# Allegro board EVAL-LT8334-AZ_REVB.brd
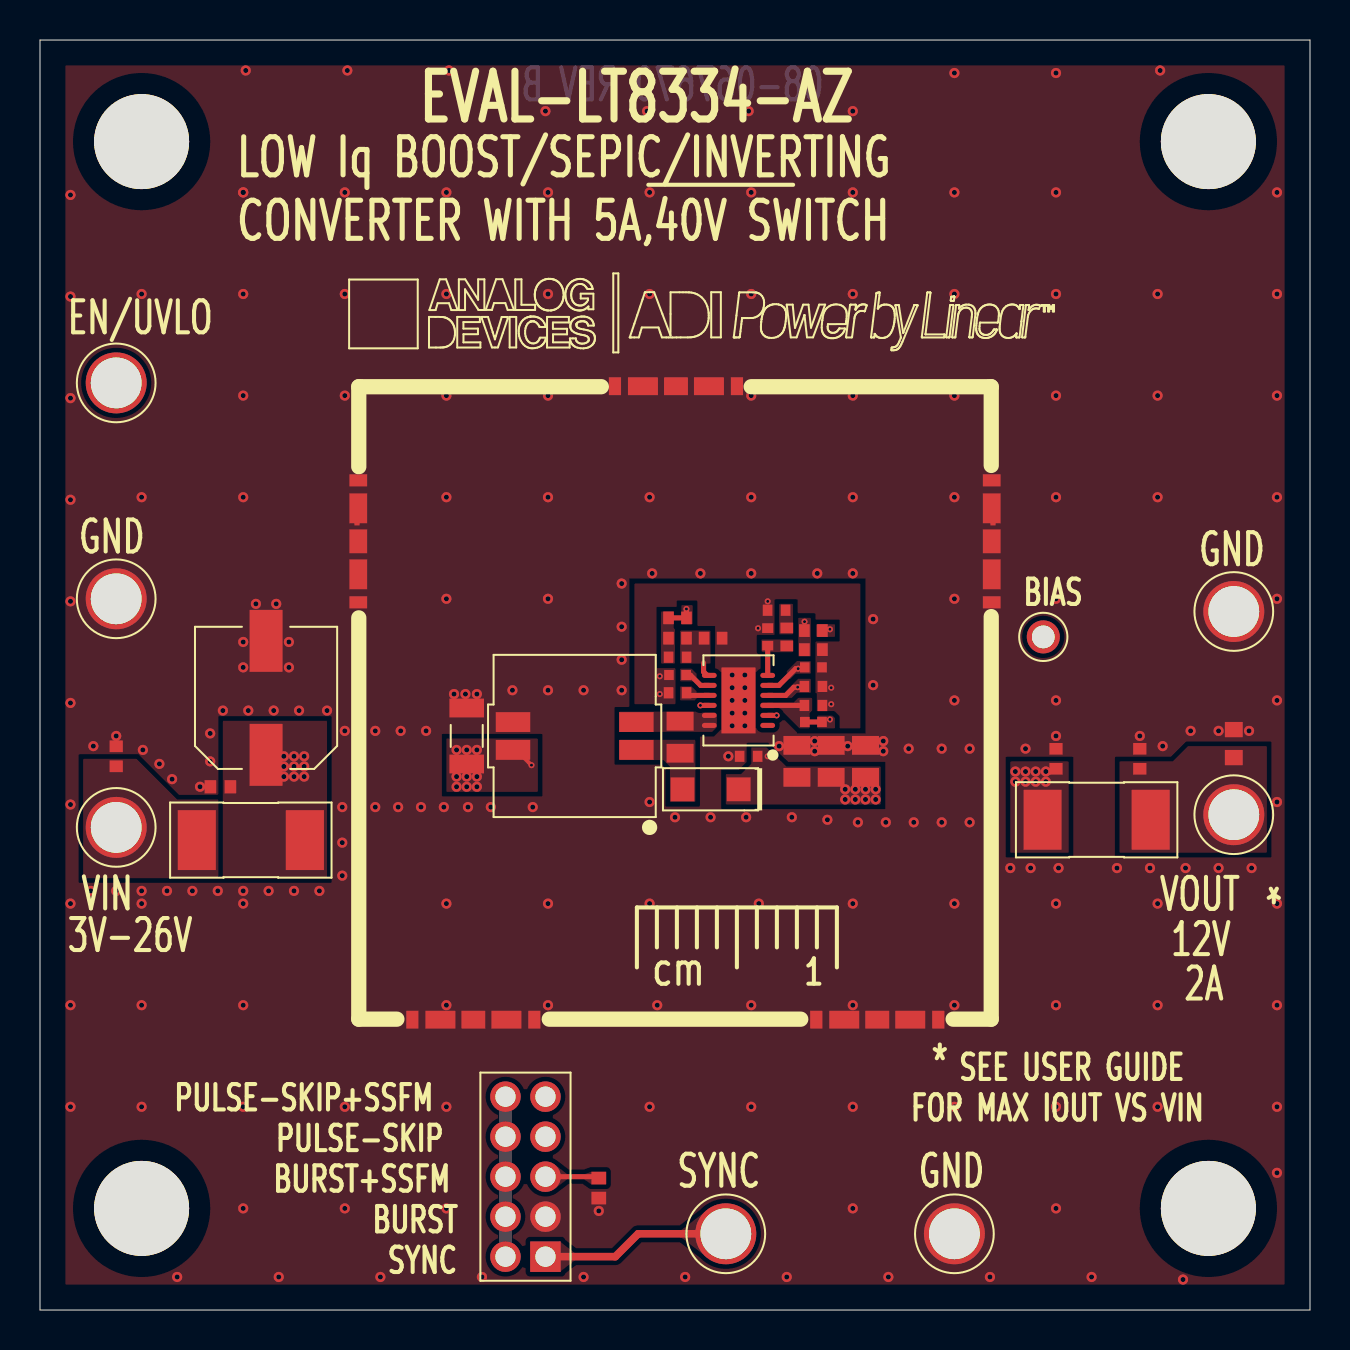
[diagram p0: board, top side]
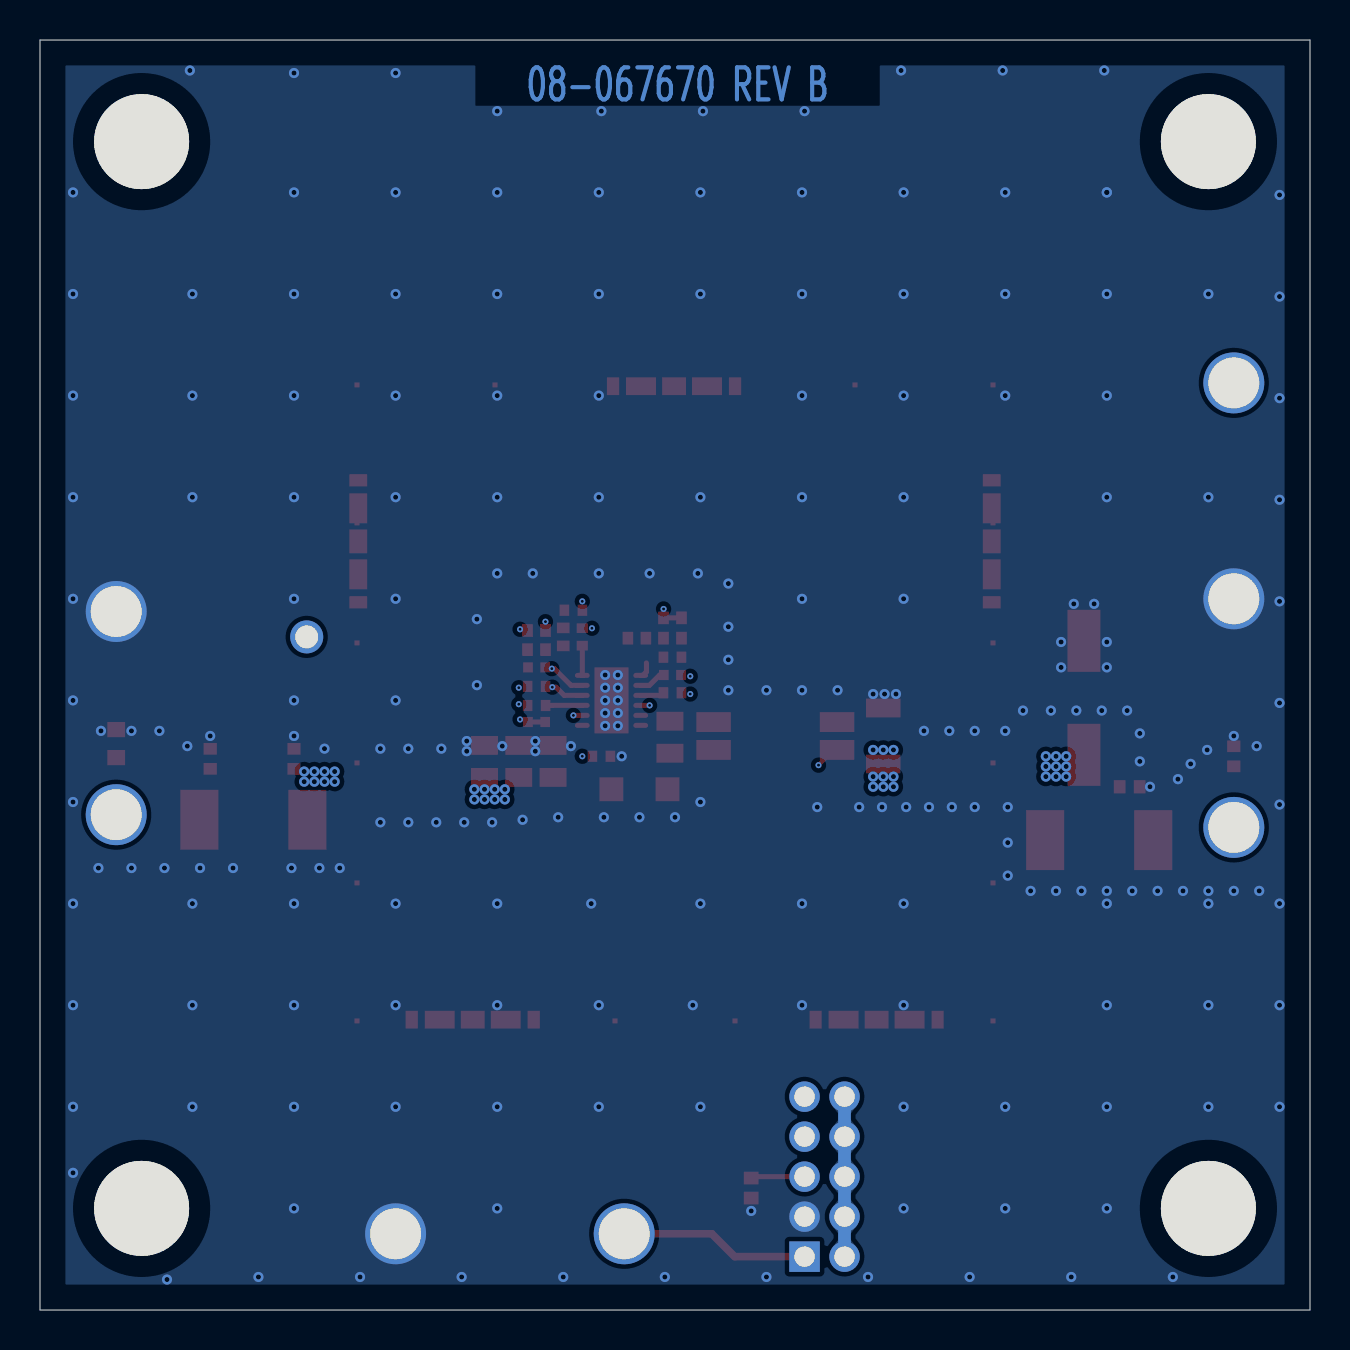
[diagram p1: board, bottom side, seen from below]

Outline 63.5 x 63.5 mm; copper layers: TOP, LAYER_2, LAYER_3, BOTTOM. Coordinates in mm from the lower left corner of the outline.
Outline path: 0,63.5 0,0 63.5,0 63.5,63.5 0,63.5

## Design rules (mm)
constraint set DEFAULT: min track width 0.203

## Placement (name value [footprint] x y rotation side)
C1  0.1UF  [C0402]  3.81 27.69 90 top
C2  0.1UF  [C0402]  9.02 26.16 180 top
C3  0.1uF  [C0402]  31.88 30.86 0 top
C4  10uF  [C1206H71]  21.34 28.7 90 top
C5  0.1UF  [C0402]  38.67 30.23 0 top
C6  4.7uF  [C0805H55]  32 28.64 270 top
C7  1000pF  [C0402]  36.83 34.99 180 top
C8  1UF  [C0402]  38.67 31.18 0 top
C9  4.7pF  [C0402]  31.88 32.64 0 top
C10  2.2UF  [C0402]  35.43 27.69 180 top
C11  22uF  [C0805H60]  37.85 27.43 90 top
C12  2.2UF  [C0402]  50.8 27.56 90 top
C13  2.2UF  [C0402]  54.99 27.56 90 top
C14  1uF  [C0603]  59.69 28.32 270 top
C15  TBD0402  [C0402#2]  36.39 33.66 90 top
C16  68UF  [CPLSMSQ260H315]  11.3 30.61 90 top
C17  22uF  [C0805H60]  41.27 27.43 90 top
C18  22uF  [C0805H60]  39.56 27.43 90 top
CL1  36900000  [CNWURTH36900000]  15.91 38.43 90 top
CL2  36900000  [CNWURTH36900000]  31.8 46.19 0 top
CL3  36900000  [CNWURTH36900000]  41.86 14.52 0 top
CL4  36900000  [CNWURTH36900000]  47.59 38.43 90 top
CL5  36900000  [CNWURTH36900000]  21.67 14.52 180 top
D1  PMEG4030ER,115  [SOD123F]  33.53 26.04 180 top
E1  2501-2-00-80-00-00-07-0  [CNMILLMAX2501]  3.81 24.13 180 top
E2  2501-2-00-80-00-00-07-0  [CNMILLMAX2501]  3.81 35.56 180 top
E3  2501-2-00-80-00-00-07-0  [CNMILLMAX2501]  3.81 46.35 180 top
E4  2501-2-00-80-00-00-07-0  [CNMILLMAX2501]  34.29 3.81 180 top
E5  2501-2-00-80-00-00-07-0  [CNMILLMAX2501]  45.72 3.81 180 top
E6  2501-2-00-80-00-00-07-0  [CNMILLMAX2501]  59.69 24.77 180 top
E7  2501-2-00-80-00-00-07-0  [CNMILLMAX2501]  59.69 34.92 180 top
FB1  880OHM AT 100MEGHZ  [L1812H67]  10.54 23.5 0 top
FB2  785OHM AT 100MEGHZ  [L1812H67]  52.83 24.51 0 top
JP1  87758-1016  [CNTHMHDR2X5L390W157H234]  25.27 2.67 90 top
L1  1.986UH/7.944UH  [LSMSQ299H175_4P]  26.73 28.7 90 top
NOREF  -  []  -187.47 299.61 0 top
NOREF#2  -  []  -178.82 342.9 0 top
NOREF#3  -  []  20.32 -7.62 0 top
NOREF#4  -  []  53.98 -5.08 270 top
NOREF#5  -  []  -192.41 353.69 0 top
NOREF#6  -  []  -188.47 53.59 0 top
NOREF#7  -  []  63.5 0 90 top
NOREF#8  -  [unnamed#2]  58.42 58.42 0 top
NOREF#9  -  []  348.62 318.77 0 top
NOREF#10  -  []  76.2 344.81 0 top
NOREF#11  -  []  -222.25 -146.05 0 top
NOREF#12  -  []  -188.7 330.83 0 top
NOREF#13  -  []  -222.25 -146.05 0 top
NOREF#14  -  []  29.84 20.13 0 top
NOREF#15  -  []  63.5 63.5 180 top
NOREF#16  -  [unnamed#2]  58.42 5.08 0 top
NOREF#17  -  []  -66.04 -72.39 0 top
NOREF#18  -  []  0 0 0 top
NOREF#19  -  [unnamed#2]  5.08 58.42 0 top
NOREF#20  -  []  -222.25 -146.05 0 top
NOREF#21  -  []  0 63.5 0 top
NOREF#22  -  [unnamed#2]  5.08 5.08 0 top
NOREF#23  -  []  63.5 0 90 top
NOREF#24  -  []  0 63.5 270 top
R1  1.15MEG  [R0402#2]  38.67 33.02 0 top
R2  20K  [R0402]  31.88 31.75 180 top
R3  1MEG  [R0402#2]  38.67 33.97 0 top
R4  22K  [R0402#2]  37.34 33.66 90 top
R5  0  [R0402]  38.67 32.13 0 top
R6  1MEG  [R0402#2]  31.88 33.59 180 top
R7  154K  [R0402#2]  33.66 33.59 180 top
R8  100K  [R0402#2]  27.94 6.1 90 top
R9  TBD0402  [R0402#2]  31.88 34.61 0 top
R10  TBD0402  [R0402]  38.67 29.4 0 top
SH1  36906326S  [M36906326S]  31.75 30.35 0 top
TP1  TESTPAD  [TPC65D45]  50.16 33.66 180 top
U1  LT8334RDE#PBF  [DFN12_4X3_PAD3_3X1_7]  34.92 30.48 90 top

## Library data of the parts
C1 C2 C5 = CAP: User Part Number: UPN; Tolerance: 10; alternate symbols: (C0402L); part number: CAP_SM-0.1UF,50V,10,E048331,C0402; tolerance: 10
C3 = CAP: User Part Number: UPN; Tolerance: 10; alternate symbols: (C0402L); part number: CAP_SM-0.1UF,25V,10,E025708,C0402; tolerance: 10
C4 = CAP: Tolerance: 20; User Part Number: UPN; alternate symbols: (C1206H71L); part number: CAP_SM-10UF,50V,20,E034660,C1206H71; tolerance: 20
C6 = CAP: User Part Number: UPN; Tolerance: 10; alternate symbols: (C0805L); part number: CAP_SM-4.7UF,50V,10,E042974,C0805H55; tolerance: 10
C7 = CAP: User Part Number: UPN; Tolerance: 10; alternate symbols: (C0402L); part number: CAP_SM-1000PF,10V,10,E038307,C0402; tolerance: 10
C8 = CAP: User Part Number: UPN; Tolerance: 10; alternate symbols: (C0402L); part number: CAP_SM-1UF,25V,10,E054542,C0402; tolerance: 10
C9 = CAP: User Part Number: UPN; Tolerance: 0.25pF; alternate symbols: (C0402L); part number: CAP_SM-4.7PF,50V,0.25PF,E041689,C0402; tolerance: 0.25pF
C10 C12 C13 = CAP: User Part Number: UPN; Tolerance: 10; alternate symbols: (C0402L); part number: CAP_SM-2.2UF,25V,10,E044855,C0402; tolerance: 10
C11 C17 C18 = CAP: User Part Number: UPN; Tolerance: 20; alternate symbols: (C0805L); part number: CAP_SM-22UF,25V,20,E028881,C0805H60; tolerance: 20
C14 = CAP: User Part Number: UPN; Tolerance: 10; alternate symbols: (C0603L); part number: CAP_SM-1UF,25V,10,E034292,C0603; tolerance: 10
C15 = CAP: User Part Number: UPN; alternate symbols: (C0402L_ALT,C0402L); part number: CAP_SM-TBD0402,TBD0402,TBD0402,E000381,C0402
C16 = CAPP: Tolerance: 20; User Part Number: UPN; alternate symbols: (); part number: CAPP_SM-68UF,35V,20,E054539,CPLSMSQ260H315; tolerance: 20
CL1-CL5 = CN5P: User Part Number: UPN; Tolerance: N/A; alternate symbols: (); part number: CN5P_SM-36900000,E054569,CNWURTH36900000; tolerance: N/A
D1 = DIOSCHOTTKY: Tolerance: N/A; User Part Number: UPN; alternate symbols: (); part number: DIOSCHOTTKY_SM-PMEG4030ER,115,40V,N/A,E017661,SOD123F; tolerance: N/A
E1-E7 = CNTP1P: User Part Number: UPN; Tolerance: N/A; alternate symbols: (); part number: CNTP1P_TH-2501-2-00-80-00-00-07-0,E031108,CNMILLMAX2501; tolerance: N/A
FB1 = FERRITE: User Part Number: UPN; Tolerance: 25; alternate symbols: (L1812H67L); part number: FERRITE_SM-880OHM AT 100MEGHZ,25,E050126,L1812H67; tolerance: 25
FB2 = FERRITE: User Part Number: UPN; Tolerance: 25; alternate symbols: (); part number: FERRITE_SM-785OHM AT 100MEGHZ,25,E038761,L1812H67; tolerance: 25
JP1 = CN10P: User Part Number: UPN; Tolerance: N/A; alternate symbols: (); part number: CN10P_TH-87758-1016,E032028,CNTHMHDR2X5L390W157H234; tolerance: N/A
L1 = IND_4P_V4: Tolerance: 20; User Part Number: UPN; alternate symbols: (); part number: IND_4P_V4_SM-1.986UH/7.944UH,20,E054540,LSMSQ299H175_4P; tolerance: 20
R1 = RES: User Part Number: UPN; Tolerance: 1; alternate symbols: (R0402L); part number: RES_SM-1.15MEG,E050592,1/16W,1,R0402; tolerance: 1
R2 = RES: Tolerance: 1; User Part Number: UPN; alternate symbols: (R0402L,R0402L_ALT); part number: RES_SM-20K,E003791,1/10W,1,R0402; tolerance: 1
R3 R6 = RES: User Part Number: UPN; Tolerance: 1; alternate symbols: (R0402L); part number: RES_SM-1MEG,E003749,1/10W,1,R0402; tolerance: 1
R4 = RES: User Part Number: UPN; Tolerance: 1; alternate symbols: (R0402L); part number: RES_SM-22K,E046831,1/10W,1,R0402; tolerance: 1
R5 = RES: Tolerance: JUMPER; User Part Number: UPN; alternate symbols: (R0402L,R0402L_ALT); part number: RES_SM-0,E003438,1/10W,JUMPER,R0402; tolerance: JUMPER
R7 = RES: User Part Number: UPN; Tolerance: 1; alternate symbols: (R0402L); part number: RES_SM-154K,E025222,1/10W,1,R0402; tolerance: 1
R8 = RES: User Part Number: UPN; Tolerance: 1; alternate symbols: (R0402L,R0402L_ALT); part number: RES_SM-100K,E003796,1/10W,1,R0402; tolerance: 1
R9 R10 = RES: User Part Number: UPN; alternate symbols: (R0402L,R0402L_ALT); part number: RES_SM-TBD0402,E004049,TBD0402,TBD0402,R0402
SH1 = MOD_SHLD_20P: User Part Number: UPN; Tolerance: N/A; alternate symbols: (); part number: MOD_SHLD_20P_SM-36906326S,E054570,M36906326S; tolerance: N/A
TP1 = NCTESTPAD: Tolerance: N/A; User Part Number: UPN; alternate symbols: (); part number: NCTESTPAD_TH-TESTPAD,E013404,TPC65D45; tolerance: N/A
U1 = ADLT8334: User Part Number: UPN; Tolerance: N/A; alternate symbols: (); part number: ADLT8334_SM-LT8334RDE#PBF,E050027,DFN12_4X3_PAD3_3X1_7; tolerance: N/A

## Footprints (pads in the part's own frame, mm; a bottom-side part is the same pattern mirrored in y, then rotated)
C0402
  rect 0.584x0.66 smd: 1(-0.5,0) 2(0.5,0)
C0402#2
  rect 0.483x0.559 smd: 1(-0.438,0) 2(0.438,0)
C0603
  rect 0.762x0.889 smd: 1(-0.7,0) 2(0.7,0)
C0805H55
  rect 0.94x1.346 smd: 1(-0.8,0) 2(0.8,0)
C0805H60
  rect 0.94x1.346 smd: 1(-0.8,0) 2(0.8,0)
C1206H71
  rect 0.94x1.727 smd: 1(-1.4,0) 2(1.4,0)
CNMILLMAX2501
  round 3.048 hole 2.54: 1(0,0)
CNTHMHDR2X5L390W157H234
  rect 1.524x1.524 hole 1.016: 1(0,0)
  round 1.524 hole 1.016: 2(0,2) 3(2,0) 4(2,2) 5(4,0) 6(4,2) 7(6,0) 8(6,2) 9(8,0) 10(8,2)
CNWURTH36900000
  rect 0.61x0.889 smd: 1(-3.05,0) 5(3.05,0)
  rect 1.499x0.889 smd: 2(-1.65,0) 4(1.65,0)
  rect 1.194x0.889 smd: 3(0,0)
CPLSMSQ260H315
  rect 3.099x1.651 smd: N(2.85,0) P(-2.85,0)
DFN12_4X3_PAD3_3X1_7
  oval 0.254x0.737 smd: 1(-1.25,-1.46) 2(-0.75,-1.46) 3(-0.25,-1.46) 4(0.25,-1.46) 5(0.75,-1.46) 6(1.25,-1.46) 7(1.25,1.46) 8(0.75,1.46) 9(0.25,1.46) 10(-0.25,1.46) 11(-0.75,1.46) 12(-1.25,1.46)
  rect 3.302x1.702 smd: PAD(0,0)
L1812H67
  rect 1.905x2.997 smd: 1(-2.703,0) 2(2.703,0)
LSMSQ299H175_4P
  rect 0.991x1.727 smd: 1(-0.695,-3.086) 2(0.695,-3.086) 3(0.695,3.086) 4(-0.695,3.086)
M36906326S
  rect 0.254x0.254 smd: 1(-15.9,-15.9) 2(-9,-15.9) 3(-3,-15.9) 4(3,-15.9) 5(9,-15.9) 6(15.9,-15.9) 7(15.9,-9) 8(15.9,-3) 9(15.9,3) 10(15.9,9) 11(15.9,15.9) 12(9,15.9) 13(3,15.9) 14(-3,15.9) 15(-9,15.9) 16(-15.9,15.9) 17(-15.9,9) 18(-15.9,3) 19(-15.9,-3) 20(-15.9,-9)
R0402
  rect 0.483x0.508 smd: 1(-0.43,0) 2(0.43,0)
R0402#2
  rect 0.533x0.635 smd: 1(-0.45,0) 2(0.45,0)
SOD123F
  rect 1.194x1.194 smd: A(1.403,0) C(-1.403,0)
TPC65D45
  round 1.651 hole 1.143: 1(0,0)
unnamed#2
  round 4.75 hole 4.75 unplated: (0,0)

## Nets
GND_POWER: C1.2(N2) C2.2(N2) C3.1 C4.2(N2) C5.2(N2) C7.2(N2) C8.2(N2) C10.2(N2) C11.2(N2) C12.2(N2) C13.2(N2) C14.1 C15.2(N2) C16.N(N2) C17.2(N2) C18.2(N2) CL1.1 CL1.2 CL1.3 CL1.4 CL1.5(N5) CL2.1 CL2.2 CL2.3 CL2.4 CL2.5(N5) CL3.1 CL3.2 CL3.3 CL3.4 CL3.5(N5) CL4.1 CL4.2 CL4.3 CL4.4 CL4.5(N5) CL5.1 CL5.2 CL5.3 CL5.4 CL5.5(N5) E2.1(N1) E5.1(N1) E7.1(N1) JP1.3 L1.3 R1.2(N2) R2.2(N2) R5.2(N2) R7.1 R8.1 SH1.1 SH1.2 SH1.3 SH1.4 SH1.5 SH1.6 SH1.7 SH1.8 SH1.9(SHIELD_9) SH1.10 SH1.11 SH1.12 SH1.13 SH1.14 SH1.15 SH1.16 SH1.17 SH1.18 SH1.19 SH1.20 U1.PAD
INTVCC: C8.1 JP1.9(N9) U1.4
UNNAMED_2_ADLT8334_I42_BIAS: R5.1 TP1.1(N1) U1.5
UNNAMED_2_ADLT8334_I42_EN: E3.1(N1) R1.1 R3.1 U1.2
UNNAMED_2_ADLT8334_I42_FBX: C9.2(N2) R6.1 R7.2(N2) U1.7
UNNAMED_2_ADLT8334_I42_RT: R2.1 U1.8
UNNAMED_2_ADLT8334_I42_SS: C3.2(N2) U1.9
UNNAMED_2_ADLT8334_I42_SW1: C6.1 L1.2 U1.11 U1.12
UNNAMED_2_ADLT8334_I42_SYNC: JP1.2 JP1.4 JP1.6 JP1.8 JP1.10 U1.10
UNNAMED_2_ADLT8334_I42_VC: C15.1 R4.1 U1.6
UNNAMED_2_CAP_I5_N1: C1.1 E1.1(N1) FB1.1
UNNAMED_2_CAP_I9_N1: C2.1 C4.1 C5.1 C16.P FB1.2(N2) L1.4(N4) R3.2(N2) R10.1 R10.2(N2) U1.3(VIN)
UNNAMED_2_CAP_I28_N2: C13.1 C14.2(N2) E6.1(N1) FB2.2(N2)
UNNAMED_2_CAP_I53_N2: C6.2(N2) D1.A(P) L1.1
UNNAMED_2_CAP_I84_N1: C7.1 R4.2(N2)
UNNAMED_2_CN10P_I40_N1: E4.1(N1) JP1.1
UNNAMED_2_CN10P_I40_N5: JP1.5 R8.2(N2)
VOUT: C9.1 C10.1 C11.1 C12.1 C17.1 C18.1 D1.C FB2.1 R6.2(N2) R9.1 R9.2(N2)

Pads without a net: JP1 7; U1 1

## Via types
v1: diameter 0.508, hole 0.254, TOP to BOTTOM, 264 vias
v2: diameter 0.305, hole 0.152, TOP to BOTTOM, 16 vias

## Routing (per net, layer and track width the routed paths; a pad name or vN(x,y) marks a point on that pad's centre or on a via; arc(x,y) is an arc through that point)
GND_POWER:
  vias: v1(1.52,55.75) v1(1.52,50.67) v1(1.52,45.59) v1(1.52,40.51) v1(1.52,35.43) v1(1.52,30.35) v1(1.52,25.27) v1(1.52,20.32) v1(1.52,15.24) v1(1.52,10.16) v1(2.54,20.95) v1(2.67,28.19) v1(3.81,28.7) v1(3.81,20.95) v1(5.08,50.8) v1(5.08,40.64) v1(5.14,28) v1(5.08,20.95) v1(5.08,20.32) v1(5.08,15.24) v1(5.08,10.16) v1(5.97,27.3) v1(6.35,20.95) v1(6.6,26.54) v1(6.86,1.65) v1(7.62,20.95) v1(8,26.16) v1(8.51,28.83) v1(8.51,27.43) v1(8.89,20.95) v1(9.14,29.97) v1(10.16,55.88) v1(10.16,55.88) v1(10.16,50.8) v1(10.16,45.72) v1(10.16,40.64) v1(10.16,33.4) v1(10.16,32.13) v1(10.16,20.95) v1(10.16,20.32) v1(10.16,15.24) v1(10.16,10.16) v1(10.16,5.08) v1(10.29,61.98) v1(10.41,29.97) v1(10.79,35.31) v1(11.43,20.95) v1(11.68,29.97) v1(11.81,35.31) v1(11.94,1.65) v1(12.45,33.4) v1(12.45,32.13) v1(12.7,20.95) v1(12.95,29.97) v1(13.97,20.95) v1(14.35,29.97) v1(15.11,25.15) v1(15.11,23.37) v1(15.11,21.72) v1(15.24,55.88) v1(15.24,50.8) v1(15.24,45.72) v1(15.24,28.96) v1(15.24,10.16) v1(15.24,5.08) v1(15.37,61.98) v1(16.76,28.96) v1(16.76,25.15) v1(17.02,1.65) v1(17.91,25.15) v1(18.03,28.96) v1(19.05,25.15) v1(19.3,28.96) v1(20.19,25.15) v1(20.32,55.88) v1(20.32,50.8) v1(20.32,45.72) v1(20.32,40.64) v1(20.32,35.56) v1(20.32,20.32) v1(20.32,15.24) v1(20.32,10.16) v1(20.32,5.08) v1(20.45,61.98) v1(20.7,30.8) v1(21.27,30.8) v1(21.4,25.15) v1(21.84,30.8) v1(22.1,1.65) v1(22.54,25.15) v1(23.62,30.99) v1(24.64,25.15) v1(25.27,59.94) v1(25.4,55.88) v1(25.4,50.8) v1(25.4,45.72) v1(25.4,40.64) v1(25.4,35.56) v1(25.4,30.99) v1(25.4,20.32) v1(25.4,15.24) v1(27.18,30.99) v1(27.18,1.65) v1(27.94,4.95) v1(29.08,36.32) v1(29.08,34.16) v1(29.08,32.51) v1(29.08,30.99) v1(30.35,59.94) v1(30.48,55.88) v1(30.48,50.8) v1(30.48,40.64) v1(30.48,25.4) v1(30.48,20.32) v1(30.48,10.16) v1(30.61,36.83) v1(30.86,15.24) v1(31.75,24.64) v1(32.26,1.65) v1(33.02,36.83) v1(33.53,24.64) v1(34.42,27.69) v1(34.61,31.75) v1(34.61,31.11) v1(34.61,30.48) v1(34.61,29.84) v1(34.61,29.21) v1(35.24,31.75) v1(35.24,31.11) v1(35.24,30.48) v1(35.24,29.84) v1(35.24,29.21) v1(35.31,24.64) v1(35.43,59.94) v1(35.56,55.88) v1(35.56,50.8) v1(35.56,45.72) v1(35.56,40.64) v1(35.56,36.83) v1(35.56,15.24) v1(35.56,10.16) v1(35.94,20.32) v1(36.96,28.19) v1(37.34,1.65) v1(37.59,24.64) v1(38.73,28.45) v1(38.73,27.94) v1(38.86,36.83) v1(39.37,24.51) v1(40.39,28.19) v1(40.64,59.94) v1(40.64,55.88) v1(40.64,50.8) v1(40.64,45.72) v1(40.64,40.64) v1(40.64,36.83) v1(40.64,20.32) v1(40.64,15.24) v1(40.64,10.16) v1(40.64,5.08) v1(40.89,24.38) v1(41.66,34.54) v1(41.66,31.24) v1(42.16,28.45) v1(42.16,27.94) v1(42.29,24.38) v1(42.42,1.65) v1(43.43,28.07) v1(43.69,24.38) v1(45.09,28.07) v1(45.09,24.38) v1(45.72,61.85) v1(45.72,55.88) v1(45.72,50.8) v1(45.72,45.72) v1(45.72,40.64) v1(45.72,35.56) v1(45.72,30.48) v1(45.72,20.32) v1(45.72,15.24) v1(45.72,10.16) v1(46.48,28.07) v1(46.48,24.38) v1(47.5,1.65) v1(48.51,22.1) v1(49.28,28.07) v1(49.53,22.1) v1(50.8,61.85) v1(50.8,55.88) v1(50.8,50.8) v1(50.8,45.72) v1(50.8,40.64) v1(50.8,35.56) v1(50.8,30.48) v1(50.8,28.7) v1(50.8,20.32) v1(50.8,15.24) v1(50.8,10.16) v1(50.8,5.08) v1(50.93,22.1) v1(52.58,1.65) v1(53.85,22.1) v1(54.99,28.7) v1(55.5,22.1) v1(55.88,50.8) v1(55.88,45.72) v1(55.88,40.64) v1(55.88,20.32) v1(55.88,15.24) v1(55.88,10.16) v1(56.01,61.98) v1(56.13,28.19) v1(57.15,1.52) v1(57.28,22.1) v1(57.53,28.96) v1(58.93,28.96) v1(58.93,22.1) v1(60.45,28.96) v1(60.58,22.1) v1(61.85,55.88) v1(61.85,50.8) v1(61.85,45.72) v1(61.85,40.64) v1(61.85,35.56) v1(61.85,30.48) v1(61.85,25.4) v1(61.85,20.32) v1(61.85,15.24) v1(61.85,10.16) v1(61.85,6.86) v2(30.99,31.69) v2(30.99,30.8) v2(35.9,34.09) v2(36.39,35.43) v2(39.56,31.11) v2(39.56,30.29)
INTVCC: length 31.9
  TOP w0.254: U1.4 37.29,30.73 37.7,31.14 v2(37.88,31.14) 38.08,31.14
  LAYER_3 w0.254: v2(37.88,31.14) 38.32,31.14 38.93,31.75 40.07,31.75 40.51,31.31 40.51,29.27 39.56,28.32 39.56,27.62 27.94,16 27.94,13.33 JP1.9
UNNAMED_2_ADLT8334_I42_BIAS: length 14.8
  TOP w0.254: v2(37.91,32.07) 37.78,32.07 36.95,31.23 U1.5
  LAYER_3 w0.254: v2(37.91,32.07) 38.48,32.64 39.31,32.64 40.32,33.66 TP1.1
UNNAMED_2_ADLT8334_I42_EN: length 47.2
  TOP w0.254: U1.2 v2(36.83,29.73)
  LAYER_3 w0.254: v2(36.83,29.73) 36.63,29.73 35.97,30.39 35.97,32.74 37.64,34.42 v2(38.23,34.42) 38.16,36.07 27.88,46.35 E3.1
UNNAMED_2_ADLT8334_I42_FBX: length 0.8
  TOP w0.254: U1.7 33.36,31.73 33.18,31.91 33.18,32.35
UNNAMED_2_ADLT8334_I42_RT: length 1.4
  TOP w0.254: U1.8 33.03,31.23 32.51,31.75 R2.1
UNNAMED_2_ADLT8334_I42_SS: length 1.2
  TOP w0.254: C3.2 32.46,30.73 U1.9
UNNAMED_2_ADLT8334_I42_SYNC: length 36.1
  TOP w0.254: U1.10 v2(33.02,30.23)
  LAYER_3 w0.381: JP1.10 23.27,27.46 25.4,29.59 32.38,29.59 v2(33.02,30.23)
  BOTTOM w0.635: JP1.10 JP1.8 JP1.6 JP1.4 JP1.2
UNNAMED_2_ADLT8334_I42_VC: length 1.5
  TOP w0.254: U1.6 36.39,31.73 C15.1
UNNAMED_2_CAP_I9_N1: length 27.7
  TOP w0.203: v2(24.57,27.24) 23.81,28.01 L1.4
  TOP w0.254: U1.3 37.9,30.23 C5.1 ; R10.1 R10.2
  LAYER_3 w0.241: 36.93,30.84 37.78,29.98
  LAYER_3 w0.254: 37.88,29.53 37.88,29.89 37.78,29.98 ; 37.88,29.53 37.88,27.84 36.77,26.73 25.08,26.73 v2(24.57,27.24) ; 37.88,29.53 v2(39.5,29.53) ; 36.93,30.84 36.93,32.38 38.07,33.53 38.67,33.53 39.18,34.04 v2(39.5,34.04)
  vias: v1(12.19,27.69) v1(12.19,27.18) v1(12.19,26.67) v1(12.7,27.69) v1(12.7,27.18) v1(12.7,26.67) v1(13.21,27.69) v1(13.21,27.18) v1(13.21,26.67) v1(20.83,28) v1(20.83,26.67) v1(20.83,26.16) v1(21.34,28) v1(21.34,26.67) v1(21.34,26.16) v1(21.84,28) v1(21.84,26.67) v1(21.84,26.16)
UNNAMED_2_CN10P_I40_N1: length 9.5
  TOP w0.381: JP1.1 28.77,2.67 29.91,3.81 E4.1
UNNAMED_2_CN10P_I40_N5: length 2.7
  TOP w0.254: JP1.5 27.87,6.67 R8.2
VOUT: length 11.2
  TOP w0.254: v2(32.32,35.05) R9.2 R9.1
  LAYER_3 w0.254: v2(32.32,35.05) 32.32,32.77 33.96,31.13 33.96,28.78 34.29,28.45 35.62,28.45 v2(36.39,27.69)
  vias: v1(40.26,26.04) v1(40.26,25.53) v1(40.77,26.04) v1(40.77,25.53) v1(41.27,26.04) v1(41.27,25.53) v1(41.78,26.04) v1(41.78,25.53) v1(48.77,26.92) v1(48.77,26.42) v1(49.28,26.92) v1(49.28,26.42) v1(49.78,26.92) v1(49.78,26.42) v1(50.29,26.92) v1(50.29,26.42)

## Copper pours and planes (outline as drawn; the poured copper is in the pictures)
GND_POWER on TOP: 1.27,62.23 62.23,62.23 62.23,1.27 1.27,1.27 ; 3 cut-outs
GND_POWER on BOTTOM: 1.27,62.23 62.23,62.23 62.23,1.27 1.27,1.27 ; 6 cut-outs
GND_POWER on LAYER_2: 1.27,62.23 62.23,62.23 62.23,1.27 1.27,1.27 ; 1 cut-out
GND_POWER on LAYER_3: 1.27,62.23 62.23,62.23 62.23,1.27 1.27,1.27 ; 6 cut-outs
INTVCC on TOP: 38.54,31.56 38.54,30.86 37.85,30.86 37.59,30.61 37.27,30.61 37.27,30.92 37.91,31.56
UNNAMED_2_ADLT8334_I42_BIAS on TOP: 38.54,32.45 38.54,31.81 37.78,31.81 37.53,31.56 37.34,31.56 37.34,31.94 37.85,32.45
UNNAMED_2_ADLT8334_I42_EN on TOP: 37.91,34.61 37.91,32.64 38.54,32.64 38.54,34.61
UNNAMED_2_ADLT8334_I42_FBX on TOP: 32,33.97 32,32.32 33.53,32.32 33.53,33.97
UNNAMED_2_ADLT8334_I42_SW1 on TOP: 33.85,29.91 33.85,29.15 33.6,28.91 28.96,28.91 28.96,29.92 33.07,29.92 33.08,29.91
UNNAMED_2_ADLT8334_I42_VC on TOP: 36.07,33.53 36.07,32.96 36.13,32.89 37.66,32.89 37.66,33.53
UNNAMED_2_CAP_I5_N1 on TOP: 2.16,21.59 9.27,21.59 9.27,25.53 6.86,25.53 4.83,27.56 2.16,27.56
UNNAMED_2_CAP_I9_N1 on TOP: 9.14,29.46 9.14,21.59 14.35,21.59 14.35,29.46
UNNAMED_2_CAP_I9_N1 on TOP: 24.89,25.91 20.32,25.91 20.32,28.57 24.89,28.57
UNNAMED_2_CAP_I9_N1 on TOP: 36,30.42 36,30.04 37.02,30.04 37.97,29.08 38.48,29.08 38.48,29.84 38.61,29.97 38.61,30.61 37.91,30.61 37.72,30.42
UNNAMED_2_CAP_I9_N1 on LAYER_3: 11.81,28.38 11.81,25.78 22.23,25.78 22.23,28.38
UNNAMED_2_CAP_I28_N2 on TOP: 53.98,27.43 53.98,22.86 61.34,22.86 61.34,28.19 57.4,28.19 56.64,27.43
UNNAMED_2_CAP_I53_N2 on TOP: 32.77,28.51 32.77,25.4 31.5,25.4 31.5,27.18 31.18,27.5 28.96,27.5 28.96,28.51
UNNAMED_2_CAP_I84_N1 on TOP: 36.96,33.78 36.96,35.31 37.66,35.31 37.66,33.78
VOUT on TOP: 35.56,28.13 35.56,27.3 35.05,26.8 34.29,26.8 34.29,25.27 42.04,25.27 42.04,27.18 37.32,27.18 36.32,28.13
VOUT on TOP: 31.05,34.92 31.05,32.32 31.75,32.32 31.75,34.04 31.69,34.1 31.69,34.92
VOUT on TOP: 51.44,27.43 51.44,22.86 48.51,22.86 48.51,27.43
VOUT on LAYER_3: 40.64,27.43 39.88,26.67 39.88,25.02 50.55,25.02 50.55,27.43

Small or netless copper shapes (teardrops, artwork), in the pictures only: 9 on TOP, 8 on BOTTOM, 5 on LAYER_3

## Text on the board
BOTTOM: 08-067670 REV B
User.Comments: PCB : BOTTOM | TURRETS | PCB : TOP
Ref Des/Silkscreen Top: PULSE-SKIP+SSFM | BURST+SSFM | PULSE-SKIP | BURST | SYNC | FOR MAX IOUT VS VIN | SEE USER GUIDE | BIAS | EN/UVLO | 3V-26V | GND | VIN | * | VOUT | 12V | 2A | LOW Iq BOOST/SEPIC/INVERTING | CONVERTER WITH 5A,40V SWITCH | EVAL-LT8334-AZ
ROOT_NUMBER: DATE:8-17-21
PAGE_OUTLINE: ~3.5 MIL | LAYER 2 | LAYER 3 | ROHS COMPLIANCE NOTE: | SPECIFICATIONS: | MATERIALS; | MATERIAL FAMILY; | CLADDING; | SOLDER MASK; | SILK SCREEN; | SURFACE FINISH; | TEST REQUIREMENTS; | PER IPC-4552 LATEST REVISION | HOMOGENOUS MATERIALS IN THIS BOARD SHALL BE COMPLIANT | THE EU RoHS DIRECTIVE 2002/95/EC | 100% NETLIST ELECTRICAL VERIFICATION USING CUSTOMER | SUPPLIED IPC-D-356 NETLIST FOR OPENS AND SHORTS WHEN | "GERBER DATA" IS PROVIDED. THIS VERIFICATION ALSO | REQUIRED FOR "ODB++" DATA PER EMBEDDED NETLIST. | ALL LAMINATES AND BONDING MATERIALS SHOULD BE SELECTED FROM | IPC-4101 OR IPC-4103, MINIMUM Tg>170degC, Td>300degC, | U.L. RATING OF 94 V-0 | FR406 | EXTERNAL LAYERS 2 OZ. COPPER | INTERNAL LAYERS 1 OZ. COPPER. | NOTE: IF THE LAYER STACKUP CONFLICTS WITH THE ABOVE | CLADDING SPECIFICATIONS THEN THE LAYER STACKUP SHALL | TAKE PRECEDENCE. | SHALL BE LIQUID PHOTOIMAGEABLE (LPI) APPLIED ON BOTH SIDES | OVER BARE COPPER OR GOLD AND SHALL MEET IPC-SM-840 | (LATEST REV.) CLASS 3. COLOR GLOSS BLUE | SHALL BE PERMANENT NON-CONDUCTIVE EPOXY INK, COLOR: WHITE | SYNTHETIC INKJET PRINTING ALLOWED FOR DENSE BOARDS, | COLOR: WHITE | ENIG (Electroless Nickel/Immersion Gold) | REQUIREMENTS: | 1.    REFER TO IPC-6010 SERIES (LATEST REV.), CLASS 2 FOR | FABRICATION UNLESS OTHERWISE SPECIFIED. | 2.    ACCEPTABILITY PER ANALOG DEVICES, INC. SPECIFICATION TST00115, | (LATEST REVISION.) | 3.    MODIFICATIONS TO THE ARTWORK ARE NOT ALLOWED WITHOUT | WRITTEN AUTHORIZATION. | 4.    HOLE PATTERN TOLERANCES FOR UNDIMENSIONED HOLES SHALL BE | A DIAMETER OF 0.005 INCHES FROM THEIR TRUE POSITION. | 5.    PLATED HOLE WALL THICKNESS SHALL NOT BE LESS THAN 0.001 INCH | MINIMUM AVERAGE, WITH NO READING LESS THAN .0008 BY | CROSS SECTION. | 6.    HOLE DIAMETERS APPLY AFTER PLATING. | 7.    FINISHED CONDUCTOR WIDTHS SHALL NOT BE REDUCED FROM THE | NOMINAL INDICATED ON THE MASTER PATTERN, BY MORE THAN THE | CONDUCTOR THICKNESS. | 8.    MINIMUM DESIGN LINE WIDTH IS .XXX INCH. | 9.    MINIMUM DESIGN SPACING IS .XXX INCH. | 10.    NON-FUNCTIONAL PAD REMOVAL FROM INNER SIGNAL LAYERS MAY BE | PERFORMED AFTER CUSTOMER APPROVAL. | 11.    IF PAD SIZES PROVIDED ARE NOT LARGE ENOUGH TO MAINTAIN | ANNULAR RING REQUIREMENT, MFGR. MAY REQUEST APPROVAL TO | TEAR DROP PADS TO MAINTAIN ANNULAR RING. (AT PAD TO TRACE | INTERSECTION ONLY AND ELECTRICAL INTEGRITY MUST BE MAINTAINED.) | B | DESIGN CHANGE | 16Aug21 | 06May21 | X
DIMENSION: "0"
User.11: (JUMPER)
User.15: ~3.5 MIL | LAYER 2 | LAYER 3 | PER IPC-4552 LATEST REVISION | ENIG (Electroless Nickel/Immersion Gold) | CHARACTERISTIC IMPEDANCE = 50 OHMS +/- 5% | ARTWORK LINE WIDTH FOR | IMPEDANCE CONTROLLED LINES = 0.xxx"
User.17: 08-      -07 | L2 GND/SIGNAL
User.18: 08-      -08 | L3 GND/SIGNAL
User.24: SUPPLY | POWER | CONNECT EN/UVLO | TO GND FOR SHUTDOWN | OPTIONAL | OPTIONAL FOR SYNC | IN | OUT | V | LOAD | I | A | - | +
User.45: FIGURE | SIZE | 6.0 | 10.0 | 40.0 | 45.0 | 100.0 | 187.0 | PLATED | NON-PLATED | FINISHED HOLES IN MILS | ALL UNITS ARE IN MILS | QTY | 16 | 264 | 10 | 1 | 7 | 4 | 302 | TOLERANCE/NOTES | TOTAL HOLES:
